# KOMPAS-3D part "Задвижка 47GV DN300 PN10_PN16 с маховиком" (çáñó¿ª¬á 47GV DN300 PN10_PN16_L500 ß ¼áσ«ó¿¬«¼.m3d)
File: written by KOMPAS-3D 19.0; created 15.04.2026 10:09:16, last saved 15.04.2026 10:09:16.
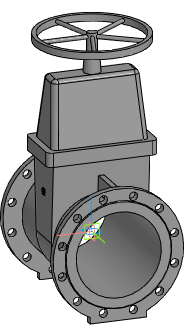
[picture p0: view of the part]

Document properties: Автор: Евгений; Полное имя файла: Z:\3.Личные\kachalov\3d для проектировщиков\2.1 Тип 47GV, 47GV.Z\Задвижка 47GV_DN40-DN600\stp_Задвижка 47GV\Задвижка 47GV DN300 PN10_PN16_L500 с маховиком.m3d

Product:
- Part/product: Задвижка 47GV DN300 PN10_PN16 с маховиком

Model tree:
1. Операция без истории:1  (labels: Задвижка 47GV DN300 PN10_PN16 с маховиком)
